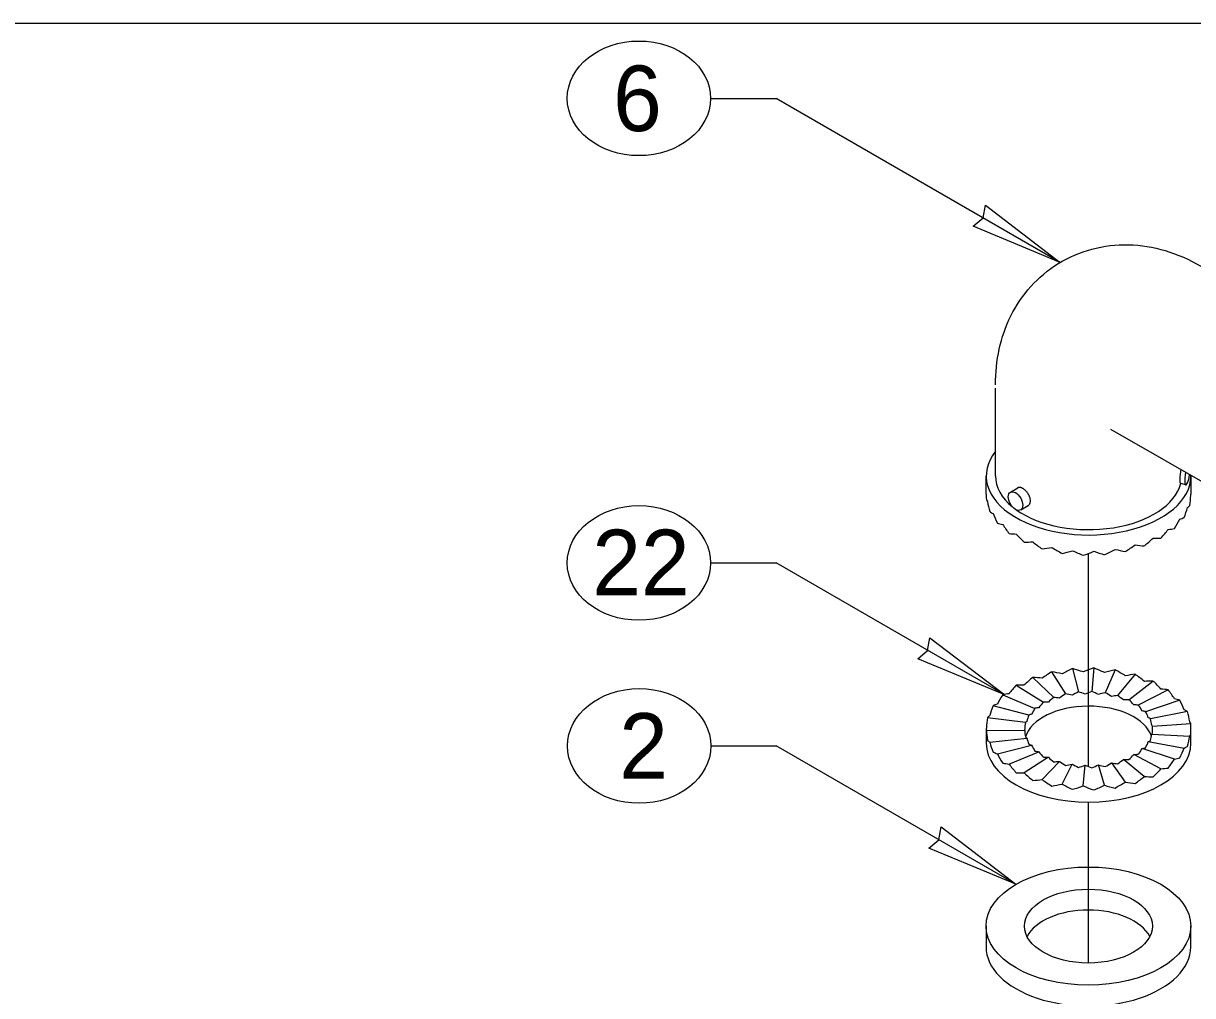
# Model space of a CAD drawing. Extents: x 99862 to 104211, y 98939 to 105076.
# Drawn here: x 100737.7 to 101023.3, y 101838 to 102075.5 of the extents above; entities that cross this region are included whole.
import ezdxf

# ---------------------------------------------------------------- set-up
doc = ezdxf.new("R2010")
doc.units = 0
for name, color, linetype in [('Level 1', 7, 'Continuous'), ('Level 15', 7, 'Continuous'), ('Level 16', 7, 'Continuous'), ('Level 2', 7, 'Continuous'), ('Level 20', 7, 'Continuous'), ('Level 22', 7, 'Continuous'), ('Level 6', 7, 'Continuous')]:
    doc.layers.add(name, color=color, linetype=linetype)

msp = doc.modelspace()

# ---------------------------------------------------------------- linework, layer by layer
at = {"layer": 'Level 1'}
msp.add_lwpolyline([(99862, 99999.5), (103151, 99999.5), (103151, 102075.5), (99862, 102075.5)], close=True, dxfattribs=at)
at = {"layer": 'Level 15'}
for p, q in [((100905.56, 102057.19), (100921.56, 102057.19)), ((100990.96, 102017.12), (100921.56, 102057.19)), ((100997.88, 101893.95), (100997.88, 101946.04)), ((100905.56, 101943.7), (100921.56, 101943.7)), ((100977.42, 101911.45), (100921.56, 101943.7)), ((100905.61, 101899), (100921.61, 101899)), ((100980.15, 101865.21), (100921.56, 101899.03)), ((100997.88, 101845.98), (100997.88, 101885.26))]:
    msp.add_line(p, q, dxfattribs=at)
for points in [[(100990.96, 102017.12), (100969.69, 102025.95), (100972.1, 102028.01), (100972.68, 102031.12)], [(100977.42, 101911.45), (100956.15, 101920.28), (100958.56, 101922.34), (100959.14, 101925.45)], [(100980.15, 101865.21), (100958.89, 101874.04), (100961.29, 101876.1), (100961.87, 101879.21)]]:
    msp.add_lwpolyline(points, close=True, dxfattribs=at)
at = {"layer": 'Level 16'}
for p, q in [((100978.79, 101961), (100980.61, 101962.04)), ((101021.6, 101962.76), (101020.37, 101963.09)), ((100981.29, 101956.67), (100983.13, 101957.73))]:
    msp.add_line(p, q, dxfattribs=at)
for centre, start_param, end_param in [((101020.77, 101965.55), 1.200429, 3.12691), ((101022, 101965.22), 1.344765, 4.7748)]:
    msp.add_ellipse(centre, major_axis=(0.38, 2.47), ratio=0.211325, start_param=start_param, end_param=end_param, dxfattribs=at)
msp.add_ellipse((100980.04, 101958.83), major_axis=(1.25, -2.17), ratio=0.57735, dxfattribs=at)
at = {"layer": 'Level 2'}
for p, q in [((100972.83, 101855), (100972.83, 101849.9)), ((101022.83, 101849.9), (101022.83, 101855))]:
    msp.add_line(p, q, dxfattribs=at)
for major_axis in [(25, 0), (15.62, 0)]:
    msp.add_ellipse((100997.83, 101855), major_axis=major_axis, ratio=0.57735, dxfattribs=at)
for major_axis, start_param, end_param in [((-15.62, 0), 3.428349, 5.996429), ((-25, 0), 0, 3.141593)]:
    msp.add_ellipse((100997.83, 101849.9), major_axis=major_axis, ratio=0.57735, start_param=start_param, end_param=end_param, dxfattribs=at)
at = {"layer": 'Level 20'}
for centre in [(100888.06, 102057.19), (100888.06, 101943.7), (100888.11, 101899)]:
    msp.add_ellipse(centre, major_axis=(-17.5, 0), ratio=0.8, dxfattribs=at)
at = {"layer": 'Level 22'}
for p, q in [((100984.26, 101915.75), (100989.37, 101910.84)), ((100992.28, 101911.7), (100988.92, 101917.12)), ((100993.97, 101917.9), (100995.43, 101912.19)), ((100999.19, 101918.06), (100998.69, 101912.29)), ((101004.35, 101917.59), (101001.92, 101911.99)), ((101009.23, 101916.51), (101004.97, 101911.32)), ((100980.2, 101913.85), (100986.83, 101909.66)), ((101007.71, 101910.29), (101013.6, 101914.86)), ((101017.31, 101912.72), (101010.02, 101908.95)), ((100976.91, 101911.51), (100984.77, 101908.19)), ((101020.15, 101910.2), (101011.8, 101907.37)), ((100983.29, 101906.51), (100974.54, 101908.82)), ((101022.03, 101907.38), (101012.97, 101905.61)), ((100982.44, 101904.69), (100973.18, 101905.9)), ((101022.84, 101904.4), (101013.48, 101903.75)), ((100972.88, 101903.16), (100972.88, 101899.7)), ((100972.91, 101902.89), (100982.27, 101902.81)), ((100982.25, 101902.97), (100982.25, 101902.81)), ((101013.31, 101901.87), (101022.57, 101901.39)), ((101013.5, 101902.19), (101013.5, 101902.97)), ((101022.88, 101899.7), (101022.88, 101903.16)), ((100973.73, 101899.91), (100982.78, 101900.94)), ((100975.6, 101897.09), (100983.96, 101899.18)), ((101018.84, 101895.78), (101010.98, 101898.36)), ((101012.46, 101900.05), (101021.22, 101898.47)), ((100978.44, 101894.56), (100985.73, 101897.6)), ((100988.05, 101896.26), (100982.15, 101892.42)), ((101011.49, 101891.54), (101006.39, 101895.71)), ((101015.55, 101893.44), (101008.93, 101896.9)), ((100986.53, 101890.78), (100990.78, 101895.24)), ((100991.41, 101889.7), (100993.83, 101894.56)), ((100996.57, 101889.23), (100997.06, 101894.27)), ((101001.79, 101889.39), (101000.32, 101894.37)), ((101003.48, 101894.86), (101006.84, 101890.17))]:
    msp.add_line(p, q, dxfattribs=at)
for centre, major_axis, ratio, start_param, end_param in [((100997.88, 101902.67), (22.83, 14.93), 0.682966, 1.726553, 1.831273), ((100997.88, 101902.67), (-24.76, 9.68), 0.360362, 5.323611, 5.42833), ((100997.88, 101902.67), (23.34, 14.49), 0.6191, 1.570348, 1.675068), ((100997.88, 101902.67), (-24.58, 11.09), 0.413044, 5.158439, 5.263158), ((100997.88, 101902.67), (23.79, 13.78), 0.557438, 1.415448, 1.520168), ((100997.88, 101902.67), (-24.32, 12.32), 0.468967, 4.997892, 5.102611), ((100997.88, 101902.67), (24.17, 12.86), 0.497899, 1.259485, 1.364205), ((100997.88, 101902.67), (-23.99, 13.35), 0.527399, 4.840753, 4.945473), ((100997.88, 101902.67), (24.46, 11.73), 0.440657, 1.100807, 1.205527), ((100997.88, 101902.67), (-23.57, 14.17), 0.588004, 4.685558, 4.790278), ((100997.88, 101902.67), (24.67, 10.41), 0.386234, 0.938087, 1.042807), ((100997.88, 101902.67), (-23.09, 14.75), 0.650745, 4.530376, 4.635096), ((100997.88, 101902.67), (22.31, 15.05), 0.749264, 1.888318, 1.993037), ((100997.88, 101902.67), (-24.87, 8.1), 0.312139, 5.494389, 5.599109), ((100997.88, 101902.67), (24.82, 8.91), 0.335596, 0.770561, 0.874936), ((100997.88, 101902.67), (-22.6, 14.92), 0.716006, 4.368664, 4.47373), ((100997.88, 101902.67), (24.91, 7.21), 0.292084, 0.595944, 0.70101), ((100997.88, 101902.67), (-22.09, 14.93), 0.783391, 4.204501, 4.308875), ((100997.88, 101902.67), (21.94, 14.64), 0.818147, 2.06586, 2.17058), ((100997.88, 101902.67), (-24.94, 6.37), 0.270119, 5.671382, 5.776101), ((100997.88, 101902.67), (-13.95, -9.4), 0.749264, 5.02991, 5.13463), ((100997.88, 101902.67), (15.54, -5.06), 0.312139, 2.352796, 2.457516), ((100997.88, 101902.67), (-14.27, -9.33), 0.682966, 4.868145, 4.972865), ((100997.88, 101902.67), (15.47, -6.05), 0.360362, 2.182018, 2.286738), ((100997.88, 101902.67), (-14.58, -9.06), 0.6191, 4.711941, 4.81666), ((100997.88, 101902.67), (15.36, -6.93), 0.413044, 2.016846, 2.121566), ((100997.88, 101902.67), (-14.87, -8.62), 0.557438, 4.557041, 4.66176), ((100997.88, 101902.67), (15.2, -7.7), 0.468967, 1.856299, 1.961019), ((100997.88, 101902.67), (-15.1, -8.04), 0.497899, 4.401077, 4.505797), ((100997.88, 101902.67), (14.99, -8.34), 0.527399, 1.69916, 1.80388), ((100997.88, 101902.67), (-15.29, -7.33), 0.440657, 4.2424, 4.34712), ((100997.88, 101902.67), (14.73, -8.85), 0.588004, 1.543965, 1.648685), ((100997.88, 101902.67), (-15.42, -6.5), 0.386234, 4.07968, 4.184399), ((100997.88, 101902.67), (14.43, -9.22), 0.650745, 1.388784, 1.493503), ((100997.88, 101902.67), (-15.51, -5.57), 0.335596, 3.912154, 4.016528), ((100997.88, 101902.67), (14.13, -9.33), 0.716006, 1.227072, 1.332137), ((100997.88, 101902.67), (24.96, 5.45), 0.252109, 0.416228, 0.520948), ((100997.88, 101902.67), (-21.92, 14.08), 0.853385, 4.009326, 4.114045), ((100997.88, 101902.67), (22.18, 12.98), 0.888613, 2.295514, 2.400234), ((100997.88, 101902.67), (-24.98, 4.51), 0.236491, 5.854579, 5.959298), ((100997.88, 101899.7), (15.63, 0), 0.57735, 0.189293, 2.972073), ((100997.88, 101902.67), (-13.71, -9.15), 0.818147, 5.207453, 5.312172), ((100997.88, 101902.67), (15.59, -3.98), 0.270119, 2.529789, 2.634509), ((100997.88, 101902.67), (-15.57, -4.51), 0.292084, 3.737537, 3.842602), ((100997.88, 101902.67), (13.81, -9.33), 0.783391, 1.062908, 1.167282), ((100997.88, 101902.67), (-15.6, -3.41), 0.252109, 3.557821, 3.662541), ((100997.88, 101902.67), (13.7, -8.8), 0.853385, 0.867733, 0.972453), ((100997.88, 101902.67), (24.99, 3.53), 0.223561, 0.230203, 0.334923), ((100997.88, 101902.67), (-22.99, 10.64), 0.922162, 3.702024, 3.806744), ((100997.88, 101902.67), (24.57, 4.88), 0.947565, 2.798423, 2.903143), ((100997.88, 101902.67), (-24.99, 2.54), 0.213589, 6.04308, 6.1478), ((100997.88, 101902.67), (-15.36, -3.05), 0.947565, 5.940016, 6.044735), ((100997.88, 101902.67), (15.62, -1.59), 0.213589, 2.901488, 3.006207), ((100997.88, 101902.67), (-13.86, -8.11), 0.888613, 5.437107, 5.541827), ((100997.88, 101902.67), (15.61, -2.82), 0.236491, 2.712986, 2.817706), ((100997.88, 101902.67), (-15.62, -2.21), 0.223561, 3.371796, 3.476515), ((100997.88, 101902.67), (14.37, -6.65), 0.922162, 0.560431, 0.665151), ((100997.88, 101902.67), (-15.62, -0.96), 0.206802, 3.181297, 3.286017), ((100997.88, 101902.67), (25, 1.53), 0.206802, 0.039705, 0.144424), ((100997.88, 101902.67), (24.57, 4.88), 0.947565, 6.044735, 6.149455), ((100997.88, 101902.67), (-25, 0.51), 0.203365, 6.234982, 6.339702), ((100997.88, 101902.67), (-22.99, 10.64), 0.922162, 0.455712, 0.560431), ((100997.88, 101902.67), (15.62, -0.32), 0.203365, 3.09339, 3.19811), ((100997.88, 101902.67), (14.37, -6.65), 0.922162, 3.597304, 3.702024), ((100997.88, 101902.67), (-15.62, -0.96), 0.206802, 0.144424, 0.249144), ((100997.88, 101902.67), (-13.86, -8.11), 0.888613, 2.400234, 2.504954), ((100997.88, 101902.67), (15.62, -0.32), 0.203365, 6.130263, 6.234982), ((100997.88, 101902.67), (-15.36, -3.05), 0.947565, 2.903143, 3.007863), ((100997.88, 101902.67), (22.18, 12.98), 0.888613, 5.541827, 5.646547), ((100997.88, 101902.67), (-25, 0.51), 0.203365, 2.98867, 3.09339), ((100997.88, 101899.7), (25, 0), 0.57735, 3.141593, 6.283185), ((100997.88, 101902.67), (25, 1.53), 0.206802, 3.286017, 3.390737), ((100997.88, 101902.67), (-21.92, 14.08), 0.853385, 0.763013, 0.867733), ((100997.88, 101902.67), (13.7, -8.8), 0.853385, 3.904606, 4.009326), ((100997.88, 101902.67), (-15.62, -2.21), 0.223561, 0.334923, 0.439643), ((100997.88, 101902.67), (13.81, -9.33), 0.783391, 4.099781, 4.204501), ((100997.88, 101902.67), (-13.95, -9.4), 0.749264, 1.993037, 2.097757), ((100997.88, 101902.67), (15.61, -2.82), 0.236491, 5.749859, 5.854579), ((100997.88, 101902.67), (-13.71, -9.15), 0.818147, 2.17058, 2.2753), ((100997.88, 101902.67), (15.62, -1.59), 0.213589, 5.93836, 6.04308), ((100997.88, 101902.67), (21.94, 14.64), 0.818147, 5.312172, 5.416892), ((100997.88, 101902.67), (-24.99, 2.54), 0.213589, 2.796768, 2.901488), ((100997.88, 101902.67), (24.99, 3.53), 0.223561, 3.476515, 3.581235), ((100997.88, 101902.67), (-22.09, 14.93), 0.783391, 0.958188, 1.062908), ((100997.88, 101902.67), (-15.6, -3.41), 0.252109, 0.520948, 0.625322), ((100997.88, 101902.67), (14.13, -9.33), 0.716006, 4.263599, 4.368664), ((100997.88, 101902.67), (-15.57, -4.51), 0.292084, 0.70101, 0.806075), ((100997.88, 101902.67), (14.43, -9.22), 0.650745, 4.426002, 4.530376), ((100997.88, 101902.67), (-14.58, -9.06), 0.6191, 1.675068, 1.779788), ((100997.88, 101902.67), (15.54, -5.06), 0.312139, 5.389669, 5.494389), ((100997.88, 101902.67), (-14.27, -9.33), 0.682966, 1.831273, 1.935992), ((100997.88, 101902.67), (15.59, -3.98), 0.270119, 5.566662, 5.671382), ((100997.88, 101902.67), (22.31, 15.05), 0.749264, 5.13463, 5.23935), ((100997.88, 101902.67), (-24.98, 4.51), 0.236491, 2.608266, 2.712986), ((100997.88, 101902.67), (24.96, 5.45), 0.252109, 3.662541, 3.766915), ((100997.88, 101902.67), (-22.6, 14.92), 0.716006, 1.122007, 1.227072), ((100997.88, 101902.67), (-15.51, -5.57), 0.335596, 0.874936, 0.979655), ((100997.88, 101902.67), (14.73, -8.85), 0.588004, 4.580838, 4.685558), ((100997.88, 101902.67), (-15.42, -6.5), 0.386234, 1.042807, 1.147526), ((100997.88, 101902.67), (14.99, -8.34), 0.527399, 4.736033, 4.840753), ((100997.88, 101902.67), (-15.29, -7.33), 0.440657, 1.205527, 1.310247), ((100997.88, 101902.67), (15.2, -7.7), 0.468967, 4.893172, 4.997892), ((100997.88, 101902.67), (-15.1, -8.04), 0.497899, 1.364205, 1.468924), ((100997.88, 101902.67), (15.36, -6.93), 0.413044, 5.053719, 5.158439), ((100997.88, 101902.67), (-14.87, -8.62), 0.557438, 1.520168, 1.624888), ((100997.88, 101902.67), (15.47, -6.05), 0.360362, 5.218891, 5.323611), ((100997.88, 101902.67), (22.83, 14.93), 0.682966, 4.972865, 5.077585), ((100997.88, 101902.67), (-24.94, 6.37), 0.270119, 2.425069, 2.529789), ((100997.88, 101902.67), (24.91, 7.21), 0.292084, 3.842602, 3.947667), ((100997.88, 101902.67), (-23.09, 14.75), 0.650745, 1.284409, 1.388784), ((100997.88, 101902.67), (24.82, 8.91), 0.335596, 4.016528, 4.121248), ((100997.88, 101902.67), (-23.57, 14.17), 0.588004, 1.439246, 1.543965), ((100997.88, 101902.67), (24.67, 10.41), 0.386234, 4.184399, 4.289119), ((100997.88, 101902.67), (-23.99, 13.35), 0.527399, 1.59444, 1.69916), ((100997.88, 101902.67), (23.79, 13.78), 0.557438, 4.66176, 4.76648), ((100997.88, 101902.67), (-24.76, 9.68), 0.360362, 2.077298, 2.182018), ((100997.88, 101902.67), (23.34, 14.49), 0.6191, 4.81666, 4.92138), ((100997.88, 101902.67), (-24.87, 8.1), 0.312139, 2.248076, 2.352796), ((100997.88, 101902.67), (24.46, 11.73), 0.440657, 4.34712, 4.45184), ((100997.88, 101902.67), (-24.32, 12.32), 0.468967, 1.751579, 1.856299), ((100997.88, 101902.67), (24.17, 12.86), 0.497899, 4.505797, 4.610517), ((100997.88, 101902.67), (-24.58, 11.09), 0.413044, 1.912126, 2.016846)]:
    msp.add_ellipse(centre, major_axis=major_axis, ratio=ratio, start_param=start_param, end_param=end_param, dxfattribs=at)
at = {"layer": 'Level 6'}
for p, q in [((100975.15, 101964.96), (100975.15, 101986.43)), ((101003.27, 101976.42), (101035, 101958.11)), ((100972.88, 101960.47), (100972.88, 101964.96)), ((101022.88, 101964.96), (101022.88, 101960.47))]:
    msp.add_line(p, q, dxfattribs=at)
for centre, major_axis, ratio, start_param, end_param in [((100997.88, 101964.96), (25, 0), 0.57735, 2.711893, 6.283185), ((100997.88, 101964.96), (22.73, 0), 0.57735, 3.141593, 3.756223), ((100997.88, 101964.96), (25, 0), 0.57735, 0, 0.010299), ((100997.88, 101964.96), (22.73, 0), 0.57735, 3.823224, 6.140086), ((100997.88, 101960.96), (-24.57, -4.88), 0.947565, 6.097095, 6.149455), ((100997.88, 101960.96), (-25, -1.53), 0.206802, 0.039705, 0.144424), ((100997.88, 101960.96), (22.99, -10.64), 0.922162, 3.702024, 3.806744), ((100997.88, 101960.96), (-24.57, -4.88), 0.947565, 2.798769, 2.903143), ((100997.88, 101960.96), (25, -0.51), 0.203365, 6.234982, 6.287342), ((100997.88, 101960.96), (-24.99, -3.53), 0.223561, 0.230203, 0.334923), ((100997.88, 101960.96), (21.92, -14.08), 0.853385, 4.009326, 4.114045), ((100997.88, 101960.96), (-22.29, -12.74), 0.887795, 2.305204, 2.41027), ((100997.88, 101960.96), (24.99, -2.53), 0.21596, 6.043201, 6.148266), ((100997.88, 101960.96), (-24.96, -5.45), 0.252109, 0.416228, 0.520948), ((100997.88, 101960.96), (22.09, -14.93), 0.783391, 4.204501, 4.309221), ((100997.88, 101960.96), (-21.94, -14.64), 0.818147, 2.06586, 2.17058), ((100997.88, 101960.96), (24.98, -4.51), 0.236491, 5.854579, 5.958953), ((100997.88, 101960.96), (-24.91, -7.25), 0.290225, 0.596374, 0.701094), ((100997.88, 101960.96), (22.56, -15.04), 0.715795, 4.372134, 4.476854), ((100997.88, 101960.96), (-22.82, -14.93), 0.682966, 1.726553, 1.831273), ((100997.88, 101960.96), (24.87, -8.1), 0.312139, 5.494389, 5.599109), ((100997.88, 101960.96), (-22.31, -15.05), 0.749264, 1.888318, 1.993037), ((100997.88, 101960.96), (24.94, -6.37), 0.270119, 5.671382, 5.776101), ((100997.88, 101960.96), (-24.82, -8.91), 0.335596, 0.770216, 0.874936), ((100997.88, 101960.96), (23.08, -14.75), 0.650745, 4.530376, 4.635096), ((100997.88, 101960.96), (-24.67, -10.41), 0.386234, 0.938087, 1.042807), ((100997.88, 101960.96), (23.57, -14.17), 0.588004, 4.685558, 4.790278), ((100997.88, 101960.96), (-23.79, -13.78), 0.557438, 1.415448, 1.520168), ((100997.88, 101960.96), (24.58, -11.09), 0.413044, 5.158439, 5.263158), ((100997.88, 101960.96), (-23.33, -14.49), 0.6191, 1.570348, 1.675068), ((100997.88, 101960.96), (24.75, -9.68), 0.360362, 5.323611, 5.42833), ((100997.88, 101960.96), (-24.46, -11.73), 0.440657, 1.100807, 1.205527), ((100997.88, 101960.96), (23.99, -13.35), 0.527399, 4.840753, 4.945473), ((100997.88, 101960.96), (-24.17, -12.86), 0.497899, 1.259485, 1.364205), ((100997.88, 101960.96), (24.32, -12.32), 0.468967, 4.997892, 5.102611)]:
    msp.add_ellipse(centre, major_axis=major_axis, ratio=ratio, start_param=start_param, end_param=end_param, dxfattribs=at)
for points in [[(100975.15, 101987.23), (100975.17, 101993.11), (100977.47, 102004.68), (100989.45, 102018.28), (101007.63, 102023.21), (101019.68, 102019.43), (101025.31, 102016.19)], [(100983.47, 101959.9), (100983.37, 101960.15), (100983.24, 101960.4), (100983.08, 101960.64), (100982.93, 101960.87), (100982.75, 101961.09), (100982.56, 101961.29), (100982.38, 101961.48), (100982.17, 101961.65), (100981.97, 101961.79), (100981.78, 101961.92), (100981.57, 101962.02), (100981.39, 101962.08), (100981.2, 101962.14), (100981.03, 101962.16), (100980.87, 101962.14), (100980.72, 101962.11), (100980.58, 101962.05), (100980.47, 101961.94)], [(100983.47, 101959.9), (100983.37, 101960.15), (100983.24, 101960.4), (100983.08, 101960.64), (100982.93, 101960.87), (100982.75, 101961.09), (100982.56, 101961.29), (100982.38, 101961.48), (100982.17, 101961.65), (100981.97, 101961.79), (100981.78, 101961.92), (100981.57, 101962.02), (100981.39, 101962.08), (100981.2, 101962.14), (100981.03, 101962.16), (100980.87, 101962.14), (100980.72, 101962.11), (100980.58, 101962.05), (100980.47, 101961.94)], [(100983.13, 101957.73), (100983.28, 101957.82), (100983.4, 101957.95), (100983.49, 101958.12), (100983.58, 101958.28), (100983.64, 101958.48), (100983.66, 101958.7), (100983.68, 101958.92), (100983.67, 101959.16), (100983.61, 101959.4), (100983.58, 101959.57), (100983.53, 101959.73), (100983.47, 101959.9)], [(100983.13, 101957.73), (100983.28, 101957.82), (100983.4, 101957.95), (100983.49, 101958.12), (100983.58, 101958.28), (100983.64, 101958.48), (100983.66, 101958.7), (100983.68, 101958.92), (100983.67, 101959.16), (100983.61, 101959.4), (100983.58, 101959.57), (100983.53, 101959.73), (100983.47, 101959.9)]]:
    msp.add_open_spline(points, degree=3, dxfattribs=at)

# ---------------------------------------------------------------- texts
at = {"layer": 'Level 20'}
msp.add_text('6', height=16, dxfattribs=at).set_placement((100881.75, 102049.19))
for s, p in [('22', (100876.66, 101935.83)), ('2', (100883.24, 101891.01))]:
    msp.add_text(s, height=16, rotation=360, dxfattribs=at).set_placement(p)

doc.saveas('drawing.dxf')
